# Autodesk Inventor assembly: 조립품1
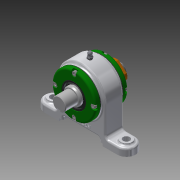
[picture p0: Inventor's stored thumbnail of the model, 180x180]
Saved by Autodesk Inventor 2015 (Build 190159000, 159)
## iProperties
Created: 2019-05
Part Number: 조립품1
Document SubType Name: Assembly
Designer: now
Author: now
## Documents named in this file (13)
- C:\Users\now\Desktop\490504V1037\조립품1.iam
- C:\Users\now\Desktop\490504V1037\개스킷.ipt
- C:\Users\now\Desktop\490504V1037\그리스니플 M6.ipt
- 그리스니플  M6.ipt
- C:\Users\now\Desktop\490504V1037\그리스니플개스킷.ipt
- C:\Users\now\Desktop\490504V1037\베어링너트.ipt
- C:\Users\now\Desktop\490504V1037\본체.ipt
- C:\Users\now\Desktop\490504V1037\볼트 M4.ipt
- C:\Users\now\Desktop\490504V1037\앵귤러 볼 베어링 7205.ipt
- C:\Users\now\Desktop\490504V1037\오일 실 28 40 5 B.ipt
- C:\Users\now\Desktop\490504V1037\축.ipt
- C:\Users\now\Desktop\490504V1037\칼라.ipt
- C:\Users\now\Desktop\490504V1037\커버.ipt
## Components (4 placed, 3 different names)
1. 개스킷:1
2. 그리스니플  M6:1
3. 그리스니플개스킷:1
4. 개스킷:2
